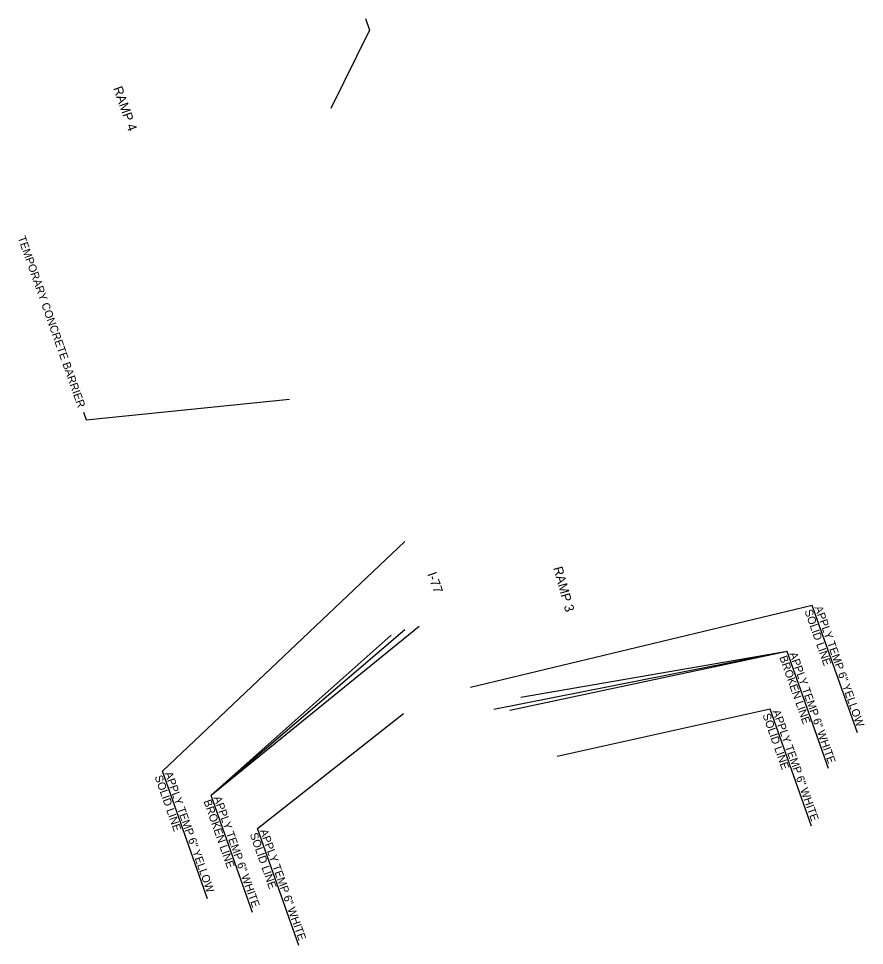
# Model space of a CAD drawing. Extents: x 2004770 to 2007199, y 1133765 to 1140032.
# Drawn here: x 2006122 to 2006757, y 1135426 to 1136121 of the extents above; entities that cross this region are included whole.
import ezdxf

# ---------------------------------------------------------------- set-up
doc = ezdxf.new("R2010")
doc.units = 0
doc.layers.add('RD_PD_MedBWall', color=7, linetype='Continuous')
doc.layers.add('RD_XS_Base', color=7, linetype='Continuous')

msp = doc.modelspace()

# ---------------------------------------------------------------- linework, layer by layer
at = {"layer": 'RD_PD_MedBWall'}
for p, q in [((2006751.48, 1135585.77), (2006717.65, 1135681.41)), ((2006266.76, 1135539.2), (2006422.78, 1135665.9)), ((2006266.76, 1135539.2), (2006411.98, 1135663.46)), ((2006698.78, 1135646.74), (2006490.81, 1135602.53)), ((2006698.78, 1135646.74), (2006499.04, 1135612.26)), ((2006729.78, 1135559.12), (2006698.78, 1135646.74)), ((2006717.15, 1135515.89), (2006686.15, 1135603.5)), ((2006264.06, 1135461.45), (2006230.23, 1135557.09)), ((2006297.91, 1135451.15), (2006266.91, 1135538.76)), ((2006332.64, 1135426.4), (2006301.65, 1135514.01))]:
    msp.add_line(p, q, dxfattribs=at)
for points in [[(2006382.49, 1136121.49), (2006385.57, 1136112.78), (2006356.58, 1136053.94)], [(2006171.13, 1135826.37), (2006173.14, 1135820.67), (2006325.45, 1135836.08)], [(2006230.23, 1135557.09), (2006411.98, 1135729.42)], [(2006717.65, 1135681.41), (2006461.34, 1135619.89)], [(2006266.76, 1135539.2), (2006401.82, 1135659.19)], [(2006698.78, 1135646.74), (2006478.84, 1135603.4)], [(2006301.65, 1135514.01), (2006411, 1135600.24)], [(2006686.15, 1135603.5), (2006526.34, 1135568.07)]]:
    msp.add_lwpolyline(points, dxfattribs=at)

# ---------------------------------------------------------------- texts
for s, p in [('TEMPORARY CONCRETE BARRIER', (2006121.65, 1135957.23)), ('SOLID LINE', (2006711.72, 1135677.19)), ('APPLY TEMP 6" YELLOW', (2006719.26, 1135679.86)), ('BROKEN LINE', (2006692.85, 1135642.52)), ('APPLY TEMP 6" WHITE', (2006700.39, 1135645.19)), ('SOLID LINE', (2006680.22, 1135599.28)), ('APPLY TEMP 6" WHITE', (2006687.76, 1135601.95)), ('SOLID LINE', (2006224.29, 1135552.87)), ('APPLY TEMP 6" YELLOW', (2006231.84, 1135555.54)), ('BROKEN LINE', (2006260.98, 1135534.54)), ('APPLY TEMP 6" WHITE', (2006268.52, 1135537.21)), ('SOLID LINE', (2006295.71, 1135509.79)), ('APPLY TEMP 6" WHITE', (2006303.26, 1135512.46))]:
    msp.add_text(s, height=6, rotation=289.48201, dxfattribs=at).set_placement(p)
at = {"layer": 'RD_XS_Base'}
for s, rotation, p in [('RAMP 4', 289.48201, (2006193.24, 1136069.24)), ('RAMP 3', 285.48201, (2006523.35, 1135709.5)), ('I-77', 289.48201, (2006428.89, 1135705))]:
    msp.add_text(s, height=7, rotation=rotation, dxfattribs=at).set_placement(p)

doc.saveas('drawing.dxf')
